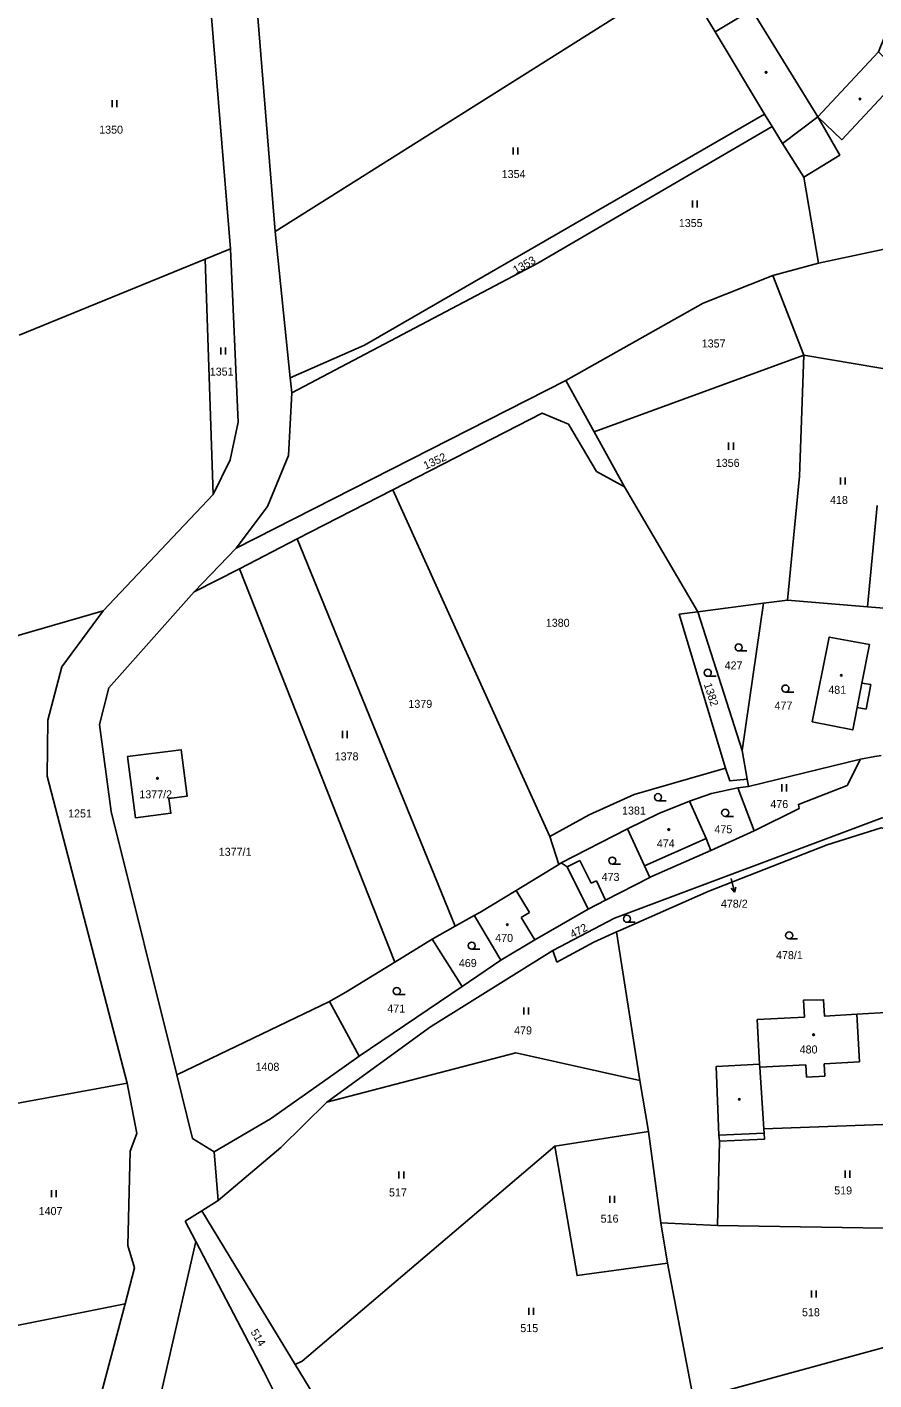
# Model space of a CAD drawing. Extents: x -520431 to -517205, y -1075927 to -1074013.
# Drawn here: x -518119.2 to -517939.3, y -1075524.8 to -1075237.3 of the extents above; entities that cross this region are included whole.
import ezdxf

# ---------------------------------------------------------------- set-up
doc = ezdxf.new("R2010")
doc.units = 0
for name, color, linetype in [('Hranice parcel', 7, 'Continuous'), ('Parcelní čísla', 7, 'Continuous'), ('Pop  PČ popisy', 7, 'Continuous'), ('Vnitřní kresba', 7, 'Continuous'), ('Značky budov', 7, 'Continuous'), ('Značky kultur', 7, 'Continuous')]:
    doc.layers.add(name, color=color, linetype=linetype)

msp = doc.modelspace()

# ---------------------------------------------------------------- linework, layer by layer
at = {"layer": 'Hranice parcel'}
for p, q in [((-518066.48, -1075280.79), (-518072.15, -1075211.03)), ((-518081.7, -1075214.82), (-518075.95, -1075284.43)), ((-518066.48, -1075280.79), (-517980.25, -1075226.41)), ((-517960.89, -1075258.47), (-517962.49, -1075255.83)), ((-517954.18, -1075269.25), (-517951.04, -1075287.46)), ((-518063.26, -1075311.84), (-518066.48, -1075280.79)), ((-517951.04, -1075287.46), (-517916.72, -1075280.21)), ((-518120.89, -1075302.8), (-518081.35, -1075286.64)), ((-518081.35, -1075286.64), (-518075.95, -1075284.43)), ((-518081.35, -1075286.64), (-518079.63, -1075336.64)), ((-517960.74, -1075290.09), (-517951.04, -1075287.46)), ((-517954.17, -1075307.01), (-517960.74, -1075290.09)), ((-517954.17, -1075307.01), (-517998.74, -1075323.3)), ((-517927.23, -1075311.64), (-517954.17, -1075307.01)), ((-518004.73, -1075312.45), (-518074.78, -1075348.03)), ((-518062.93, -1075315.03), (-518063.26, -1075311.84)), ((-517998.74, -1075323.3), (-518004.73, -1075312.45)), ((-517992.28, -1075334.99), (-517998.74, -1075323.3)), ((-518061.77, -1075346.09), (-518041.46, -1075335.66)), ((-518008.1, -1075409.28), (-518041.46, -1075335.66)), ((-517992.28, -1075334.99), (-517976.66, -1075361.57)), ((-518079.63, -1075336.64), (-518103, -1075361.39)), ((-517940.67, -1075360.49), (-517938.6, -1075338.97)), ((-518074.08, -1075352.41), (-518061.77, -1075346.09)), ((-518028.24, -1075428.37), (-518061.77, -1075346.09)), ((-518074.78, -1075348.03), (-518083.69, -1075357.35)), ((-518083.69, -1075357.35), (-518074.08, -1075352.41)), ((-518074.08, -1075352.41), (-518041.05, -1075435.98)), ((-517962.74, -1075359.74), (-517976.66, -1075361.57)), ((-517976.66, -1075361.57), (-517967.27, -1075391.06)), ((-517967.27, -1075391.06), (-517962.74, -1075359.74)), ((-517957.61, -1075359.06), (-517962.74, -1075359.74)), ((-517957.61, -1075359.06), (-517940.67, -1075360.49)), ((-517940.67, -1075360.49), (-517931.83, -1075361.23)), ((-517967.27, -1075391.06), (-517966.2, -1075397.13)), ((-517965.93, -1075398.67), (-517942.14, -1075392.85)), ((-517968.16, -1075398.96), (-517965.93, -1075398.67)), ((-517964.71, -1075408.08), (-517968.16, -1075398.96)), ((-517966.2, -1075397.13), (-517965.93, -1075398.67)), ((-518005.7, -1075414.93), (-517991.64, -1075407.68)), ((-518006.23, -1075415.25), (-518008.1, -1075409.28)), ((-517964.71, -1075408.08), (-517973.92, -1075412.26)), ((-518006.23, -1075415.25), (-518005.7, -1075414.93)), ((-518024.2, -1075426.11), (-518028.24, -1075428.37)), ((-518007.48, -1075433.53), (-517994.39, -1075426.63)), ((-518028.24, -1075428.37), (-518033.09, -1075431.09)), ((-517993.93, -1075429.57), (-517998.75, -1075431.74)), ((-517993.13, -1075429.21), (-517993.93, -1075429.57)), ((-517989, -1075461.16), (-517993.93, -1075429.57)), ((-518033.09, -1075431.09), (-518041.05, -1075435.98)), ((-518033.09, -1075431.09), (-518026.73, -1075441.14)), ((-518006.65, -1075435.97), (-518007.48, -1075433.53)), ((-517998.75, -1075431.74), (-518006.65, -1075435.97)), ((-518026.73, -1075441.14), (-518018.5, -1075435.56)), ((-518048.63, -1075455.98), (-518026.73, -1075441.14)), ((-518054.9, -1075444.38), (-518087.38, -1075459.95)), ((-518054.9, -1075444.38), (-518048.63, -1075455.98)), ((-517987.19, -1075471.97), (-517989, -1075461.16)), ((-517987.19, -1075471.97), (-518007.07, -1075475.08)), ((-517984.54, -1075491.39), (-517987.19, -1075471.97)), ((-518079.43, -1075476.29), (-518078.55, -1075486.63)), ((-517972.1, -1075474), (-517972.53, -1075491.96)), ((-518078.55, -1075486.63), (-518082.06, -1075488.83)), ((-518082.06, -1075488.83), (-518085.57, -1075491.04)), ((-518085.57, -1075491.04), (-518083.3, -1075495.38)), ((-518062.2, -1075521.51), (-518082.06, -1075488.83)), ((-517983.14, -1075499.93), (-517984.54, -1075491.39)), ((-517972.53, -1075491.96), (-517984.54, -1075491.39)), ((-517919.03, -1075492.78), (-517972.53, -1075491.96)), ((-517977.61, -1075528.88), (-517983.14, -1075499.93)), ((-518098.36, -1075508.57), (-518129.56, -1075514.81)), ((-517977.61, -1075528.88), (-517928.42, -1075515.49)), ((-518053.92, -1075535.11), (-518062.2, -1075521.51))]:
    msp.add_line(p, q, dxfattribs=at)
for points in [[(-517962.49, -1075255.83), (-517973.03, -1075238.37), (-517980.25, -1075226.41)], [(-517936.98, -1075239.29), (-517938.32, -1075242.61), (-517933.25, -1075247.53), (-517946.07, -1075261.28), (-517951.17, -1075256.42), (-517946.52, -1075264.53), (-517954.18, -1075269.25)], [(-517962.49, -1075255.83), (-518047.5, -1075304.93), (-518063.26, -1075311.84)], [(-518062.93, -1075315.03), (-518010.68, -1075287.52), (-517960.89, -1075258.47)], [(-517954.18, -1075269.25), (-517958.73, -1075262.05), (-517960.89, -1075258.47)], [(-518075.95, -1075284.43), (-518074.36, -1075321.24), (-518076.07, -1075329.25), (-518079.63, -1075336.64)], [(-518004.73, -1075312.45), (-517975.52, -1075295.97), (-517960.74, -1075290.09)], [(-517954.17, -1075307.01), (-517955.08, -1075332.73), (-517957.61, -1075359.06)], [(-518074.78, -1075348.03), (-518068.1, -1075339.17), (-518063.66, -1075328.37), (-518062.93, -1075315.03)], [(-518041.46, -1075335.66), (-518009.72, -1075319.36), (-518004.17, -1075321.71), (-517998.19, -1075331.75), (-517992.28, -1075334.99)], [(-518087.38, -1075459.95), (-518101.32, -1075403.97), (-518103.76, -1075385.54), (-518101.78, -1075377.74), (-518083.69, -1075357.35)], [(-518662.74, -1075523.4), (-518476.17, -1075469.4), (-518289.59, -1075415.4), (-518103, -1075361.39)], [(-518103, -1075361.39), (-518111.82, -1075373.25), (-518114.8, -1075384.58), (-518114.94, -1075396.5), (-518097.89, -1075461.73)], [(-517970.83, -1075394.75), (-517980.63, -1075362.09), (-517976.66, -1075361.57)], [(-517941.83, -1075376.71), (-517942.86, -1075381.92), (-517943.78, -1075386.64), (-517952.36, -1075384.94), (-517948.77, -1075366.92), (-517940.22, -1075368.52), (-517941.83, -1075376.71)], [(-518096.17, -1075405.35), (-518097.87, -1075392.32), (-518086.42, -1075390.88), (-518085.15, -1075400.7), (-518089.03, -1075401.2), (-518088.61, -1075404.37), (-518096.17, -1075405.35)], [(-517942.14, -1075392.85), (-517944.97, -1075398.44), (-517955.33, -1075402.5), (-517955.13, -1075403.32), (-517964.71, -1075408.08)], [(-517937.71, -1075392.09), (-517939.06, -1075392.31), (-517942.14, -1075392.85)], [(-518008.1, -1075409.28), (-517999.74, -1075404.69), (-517990.24, -1075400.35), (-517970.83, -1075394.75)], [(-517966.2, -1075397.13), (-517969.91, -1075397.44), (-517970.83, -1075394.75)], [(-517978.47, -1075401.82), (-517973.77, -1075400.16), (-517968.16, -1075398.96)], [(-517991.64, -1075407.68), (-517984.96, -1075404.41), (-517978.47, -1075401.82)], [(-517973.92, -1075412.26), (-517974.94, -1075409.72), (-517978.47, -1075401.82)], [(-517994.39, -1075426.63), (-517937.53, -1075405.32), (-517933.11, -1075406.32)], [(-517931.42, -1075410.32), (-517932.87, -1075408.62), (-517937.73, -1075407.46), (-517949.18, -1075411.04), (-517974.33, -1075420.92), (-517993.13, -1075429.21)], [(-517986.88, -1075417.98), (-517988, -1075415.55), (-517991.64, -1075407.68)], [(-517973.92, -1075412.26), (-517986.65, -1075417.86), (-517986.88, -1075417.98)], [(-518024.2, -1075426.11), (-518022.98, -1075425.43), (-518015.29, -1075420.76), (-518006.23, -1075415.25)], [(-518000.01, -1075424.75), (-518004.45, -1075415.73), (-518005.7, -1075414.93)], [(-517986.88, -1075417.98), (-517996.28, -1075422.8), (-518000.01, -1075424.75)], [(-518000.01, -1075424.75), (-518011.32, -1075431.23), (-518018.5, -1075435.56)], [(-518018.5, -1075435.56), (-518024.16, -1075426.18), (-518024.2, -1075426.11)], [(-518055.52, -1075465.72), (-518033.47, -1075449.74), (-518007.48, -1075433.53)], [(-518041.05, -1075435.98), (-518051.08, -1075442.15), (-518054.9, -1075444.38)], [(-517972.1, -1075474), (-517972.19, -1075472.75), (-517972.82, -1075458.18), (-517963.56, -1075457.68), (-517964.06, -1075448.19), (-517954.03, -1075447.66), (-517954.22, -1075444.06), (-517949.97, -1075444), (-517949.79, -1075447.44), (-517942.91, -1075447.08), (-517935.48, -1075446.62), (-517934.91, -1075456.75), (-517922.74, -1075456.36)], [(-518048.63, -1075455.98), (-518053.99, -1075459.83), (-518067.44, -1075469.3), (-518079.43, -1075476.29)], [(-518055.52, -1075465.72), (-518015.38, -1075455.27), (-517989, -1075461.16)], [(-518097.89, -1075461.73), (-518132.07, -1075467.93), (-518129.56, -1075514.81)], [(-518097.89, -1075461.73), (-518095.86, -1075472.37), (-518097.25, -1075476.19), (-518097.77, -1075496.19), (-518096.33, -1075500.93), (-518098.36, -1075508.57)], [(-518079.43, -1075476.29), (-518084.01, -1075473.47), (-518087.38, -1075459.95)], [(-518078.55, -1075486.63), (-518065.24, -1075475.38), (-518055.52, -1075465.72)], [(-517921.87, -1075469.9), (-517962.67, -1075471.43), (-517962.61, -1075472.32), (-517962.53, -1075473.62), (-517972.1, -1075474)], [(-518007.07, -1075475.08), (-518060.75, -1075520.74), (-518062.2, -1075521.51)], [(-517983.14, -1075499.93), (-518002.35, -1075502.6), (-518007.07, -1075475.08)], [(-518107.27, -1075709.57), (-518109.82, -1075693.22), (-518114.05, -1075688.54), (-518118.33, -1075659.57), (-518116.37, -1075640), (-518115.8, -1075620.46), (-518096.66, -1075553.44), (-518083.3, -1075495.38)], [(-518083.3, -1075495.38), (-518068.88, -1075522.94), (-518061.62, -1075537.56), (-518059.46, -1075536.53)], [(-518125.69, -1075721.88), (-518120.86, -1075706.74), (-518130.94, -1075649.23), (-518129.54, -1075625.65), (-518098.36, -1075508.57)]]:
    msp.add_lwpolyline(points, dxfattribs=at)
at = {"layer": 'Pop  PČ popisy'}
for p, q in [((-517969.61, -1075418.22), (-517969.6, -1075418.24)), ((-517969.6, -1075418.24), (-517968.87, -1075421.15)), ((-517968.87, -1075421.15), (-517969.6, -1075420.3)), ((-517968.87, -1075421.15), (-517968.63, -1075420.06))]:
    msp.add_line(p, q, dxfattribs=at)
at = {"layer": 'Vnitřní kresba'}
for p, q in [((-517973.03, -1075238.37), (-517965.24, -1075233.67)), ((-517965.24, -1075233.67), (-517951.17, -1075256.42)), ((-517951.17, -1075256.42), (-517938.32, -1075242.61)), ((-517958.73, -1075262.05), (-517951.17, -1075256.42)), ((-517941.83, -1075376.71), (-517939.94, -1075377.02)), ((-517939.94, -1075377.02), (-517940.92, -1075382.28)), ((-517940.92, -1075382.28), (-517942.86, -1075381.92)), ((-517974.94, -1075409.72), (-517988, -1075415.55)), ((-518004.45, -1075415.73), (-518001.76, -1075414.41)), ((-518001.76, -1075414.41), (-517999.32, -1075419.23)), ((-517999.32, -1075419.23), (-517998.24, -1075418.73)), ((-517998.24, -1075418.73), (-517996.28, -1075422.8)), ((-518015.29, -1075420.76), (-518012.47, -1075425.45)), ((-518012.47, -1075425.45), (-518014.18, -1075426.49)), ((-518014.18, -1075426.49), (-518011.32, -1075431.23)), ((-517942.91, -1075447.08), (-517942.35, -1075457.2)), ((-517963.5, -1075458.3), (-517963.56, -1075457.68)), ((-517953.75, -1075457.79), (-517963.5, -1075458.3)), ((-517963.5, -1075458.3), (-517962.67, -1075471.43)), ((-517953.63, -1075460.45), (-517953.75, -1075457.79)), ((-517942.35, -1075457.2), (-517949.86, -1075457.59)), ((-517949.86, -1075457.59), (-517949.73, -1075460.19)), ((-517949.73, -1075460.19), (-517953.63, -1075460.45)), ((-517972.19, -1075472.75), (-517962.61, -1075472.32))]:
    msp.add_line(p, q, dxfattribs=at)
at = {"layer": 'Značky budov'}
for centre in [(-517962.17, -1075246.96), (-517942.23, -1075252.63), (-517946.21, -1075375.06), (-518091.48, -1075396.93), (-517982.85, -1075407.83), (-518017.17, -1075428.05), (-517952.1, -1075451.43), (-517967.87, -1075465.16)]:
    msp.add_circle(centre, 0.175, dxfattribs=at)
at = {"layer": 'Značky kultur'}
for p, q in [((-518101.08, -1075254.38), (-518101.08, -1075252.88)), ((-518100.08, -1075254.38), (-518100.08, -1075252.88)), ((-518015.89, -1075264.39), (-518015.89, -1075262.89)), ((-518014.89, -1075264.39), (-518014.89, -1075262.89)), ((-517977.8, -1075275.66), (-517977.8, -1075274.16)), ((-517976.8, -1075275.66), (-517976.8, -1075274.16)), ((-518078.01, -1075306.89), (-518078.01, -1075305.39)), ((-518077.01, -1075306.89), (-518077.01, -1075305.39)), ((-517970.14, -1075327.12), (-517970.14, -1075325.62)), ((-517969.14, -1075327.12), (-517969.14, -1075325.62)), ((-517946.36, -1075334.53), (-517946.36, -1075333.03)), ((-517945.36, -1075334.53), (-517945.36, -1075333.03)), ((-517968.02, -1075369.88), (-517966.27, -1075369.88)), ((-517974.57, -1075375.27), (-517972.82, -1075375.27)), ((-517958.07, -1075378.62), (-517956.32, -1075378.62)), ((-518052.2, -1075388.38), (-518052.2, -1075386.88)), ((-518051.2, -1075388.38), (-518051.2, -1075386.88)), ((-517958.86, -1075399.71), (-517958.86, -1075398.21)), ((-517957.86, -1075399.71), (-517957.86, -1075398.21)), ((-517985.14, -1075401.7), (-517983.39, -1075401.7)), ((-517970.87, -1075405.02), (-517969.12, -1075405.02)), ((-517994.86, -1075415.17), (-517993.11, -1075415.17)), ((-517991.74, -1075427.53), (-517989.99, -1075427.53)), ((-518024.72, -1075433.24), (-518022.97, -1075433.24)), ((-517957.28, -1075431.06), (-517955.53, -1075431.06)), ((-518040.63, -1075442.9), (-518038.88, -1075442.9)), ((-518013.68, -1075447.12), (-518013.68, -1075445.62)), ((-518012.68, -1075447.12), (-518012.68, -1075445.62)), ((-518040.17, -1075481.98), (-518040.17, -1075480.48)), ((-518039.17, -1075481.98), (-518039.17, -1075480.48)), ((-517945.4, -1075481.79), (-517945.4, -1075480.29)), ((-517944.4, -1075481.79), (-517944.4, -1075480.29)), ((-518113.98, -1075485.94), (-518113.98, -1075484.44)), ((-518112.98, -1075485.94), (-518112.98, -1075484.44)), ((-517995.36, -1075487.12), (-517995.36, -1075485.62)), ((-517994.36, -1075487.12), (-517994.36, -1075485.62)), ((-517952.53, -1075507.27), (-517952.53, -1075505.77)), ((-517951.53, -1075507.27), (-517951.53, -1075505.77)), ((-518012.57, -1075510.96), (-518012.57, -1075509.46)), ((-518011.57, -1075510.96), (-518011.57, -1075509.46))]:
    msp.add_line(p, q, dxfattribs=at)
for centre in [(-517968.02, -1075369.13), (-517974.57, -1075374.52), (-517958.07, -1075377.87), (-517985.14, -1075400.95), (-517970.87, -1075404.27), (-517994.86, -1075414.42), (-517991.74, -1075426.78), (-517957.28, -1075430.31), (-518024.72, -1075432.49), (-518040.63, -1075442.15)]:
    msp.add_circle(centre, 0.75, dxfattribs=at)

# ---------------------------------------------------------------- texts
at = {"layer": 'Parcelní čísla'}
for s, p in [('1350', (-518103.86, -1075259.98)), ('1354', (-518018.35, -1075269.41)), ('1355', (-517980.72, -1075279.82)), ('1357', (-517975.85, -1075305.41)), ('1351', (-518080.37, -1075311.38)), ('1356', (-517972.87, -1075330.77)), ('418', (-517948.6, -1075338.65)), ('1380', (-518008.98, -1075364.75)), ('427', (-517970.99, -1075373.8)), ('481', (-517948.97, -1075378.99)), ('1379', (-518038.17, -1075381.97)), ('477', (-517960.39, -1075382.34)), ('1378', (-518053.83, -1075393.14)), ('1377/2', (-518095.33, -1075401.19)), ('476', (-517961.28, -1075403.26)), ('1251', (-518110.46, -1075405.26)), ('1381', (-517992.78, -1075404.64)), ('475', (-517973.15, -1075408.61)), ('474', (-517985.39, -1075411.62)), ('1377/1', (-518078.46, -1075413.4)), ('473', (-517997.12, -1075418.74)), ('478/2', (-517971.78, -1075424.43)), ('470', (-518019.73, -1075431.7)), ('478/1', (-517960.07, -1075435.35)), ('469', (-518027.45, -1075437.04)), ('471', (-518042.65, -1075446.7)), ('479', (-518015.71, -1075451.35)), ('480', (-517955.05, -1075455.4)), ('1408', (-518070.64, -1075459.08)), ('517', (-518042.29, -1075485.78)), ('519', (-517947.71, -1075485.35)), ('1407', (-518116.72, -1075489.73)), ('516', (-517997.33, -1075491.34)), ('518', (-517954.55, -1075511.22)), ('515', (-518014.39, -1075514.6))]:
    msp.add_text(s, height=1.7, dxfattribs=at).set_placement(p)
for s, rotation, p in [('1353', 29, (-518015.36, -1075289.83)), ('1352', 25, (-518034.49, -1075331.38)), ('1382', 288, (-517975.42, -1075376.99)), ('472', 28, (-518003.29, -1075430.96)), ('514', 301, (-518071.78, -1075514.57))]:
    msp.add_text(s, height=1.7, rotation=rotation, dxfattribs=at).set_placement(p)

doc.saveas('drawing.dxf')
